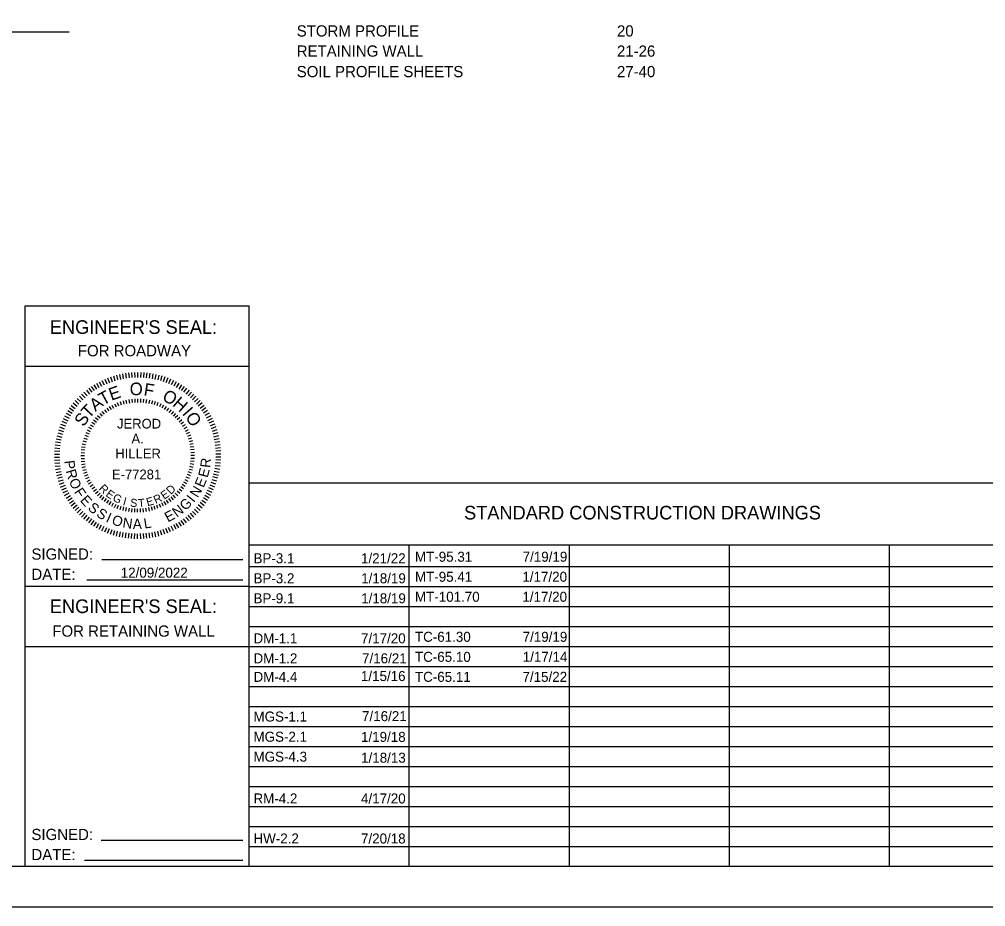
# Model space of a CAD drawing. Extents: x 0 to 34, y 0 to 22.
# Drawn here: x 8.38 to 20.45, y 0 to 11.08 of the extents above; entities that cross this region are included whole.
import ezdxf

# ---------------------------------------------------------------- set-up
doc = ezdxf.new("R2010")
doc.units = 0
for name, color, linetype in [('Default', 7, 'Continuous'), ('SH_Border', 7, 'Continuous'), ('SH_Cut_Line', 7, 'Continuous'), ('SH_Data', 7, 'Continuous'), ('SH_Text', 7, 'Continuous')]:
    doc.layers.add(name, color=color, linetype=linetype)

msp = doc.modelspace()

# ---------------------------------------------------------------- linework, layer by layer
at = {"layer": 'Default'}
for p, q in [((9.629, 6.648), (9.643, 6.586)), ((9.666, 6.656), (9.678, 6.594)), ((9.704, 6.662), (9.713, 6.6)), ((9.742, 6.667), (9.749, 6.604)), ((9.781, 6.67), (9.785, 6.608)), ((9.819, 6.673), (9.821, 6.61)), ((9.857, 6.673), (9.857, 6.61)), ((9.896, 6.673), (9.893, 6.61)), ((9.934, 6.67), (9.929, 6.608)), ((9.972, 6.667), (9.965, 6.604)), ((10.01, 6.662), (10.001, 6.6)), ((10.048, 6.656), (10.037, 6.594)), ((10.086, 6.648), (10.072, 6.586)), ((9.343, 6.537), (9.374, 6.483)), ((9.377, 6.556), (9.406, 6.5)), ((9.411, 6.573), (9.438, 6.516)), ((9.446, 6.589), (9.471, 6.531)), ((9.482, 6.603), (9.505, 6.544)), ((9.518, 6.616), (9.538, 6.557)), ((9.554, 6.628), (9.573, 6.568)), ((9.591, 6.639), (9.607, 6.578)), ((10.123, 6.639), (10.107, 6.578)), ((10.16, 6.628), (10.142, 6.568)), ((10.197, 6.616), (10.176, 6.557)), ((10.233, 6.603), (10.21, 6.544)), ((10.268, 6.589), (10.243, 6.531)), ((10.303, 6.573), (10.276, 6.516)), ((10.338, 6.556), (10.308, 6.5)), ((10.371, 6.537), (10.34, 6.483)), ((9.157, 6.402), (9.2, 6.356)), ((9.186, 6.427), (9.227, 6.379)), ((9.216, 6.452), (9.255, 6.402)), ((9.246, 6.475), (9.283, 6.424)), ((9.278, 6.497), (9.313, 6.445)), ((9.31, 6.518), (9.343, 6.464)), ((10.404, 6.518), (10.371, 6.464)), ((10.437, 6.497), (10.402, 6.445)), ((10.468, 6.475), (10.431, 6.424)), ((10.499, 6.452), (10.46, 6.402)), ((10.529, 6.427), (10.488, 6.379)), ((10.557, 6.402), (10.515, 6.356)), ((9.052, 6.291), (9.1, 6.251)), ((9.076, 6.32), (9.124, 6.278)), ((9.102, 6.348), (9.148, 6.305)), ((9.129, 6.376), (9.173, 6.331)), ((9.569, 6.281), (9.587, 6.241)), ((9.603, 6.296), (9.619, 6.254)), ((9.638, 6.308), (9.652, 6.266)), ((9.674, 6.319), (9.685, 6.276)), ((9.71, 6.327), (9.719, 6.284)), ((9.746, 6.334), (9.753, 6.29)), ((9.783, 6.339), (9.788, 6.295)), ((9.82, 6.342), (9.822, 6.298)), ((9.857, 6.343), (9.857, 6.299)), ((9.894, 6.342), (9.892, 6.298)), ((9.931, 6.339), (9.927, 6.295)), ((9.968, 6.334), (9.961, 6.29)), ((10.005, 6.327), (9.995, 6.284)), ((10.041, 6.319), (10.029, 6.276)), ((10.076, 6.308), (10.063, 6.266)), ((10.111, 6.296), (10.095, 6.254)), ((10.145, 6.281), (10.128, 6.241)), ((10.585, 6.376), (10.541, 6.331)), ((10.612, 6.348), (10.566, 6.305)), ((10.638, 6.32), (10.591, 6.278)), ((10.663, 6.291), (10.614, 6.251)), ((8.964, 6.165), (9.018, 6.133)), ((8.984, 6.197), (9.037, 6.163)), ((9.005, 6.229), (9.057, 6.193)), ((9.028, 6.26), (9.078, 6.222)), ((9.383, 6.161), (9.413, 6.128)), ((9.411, 6.185), (9.439, 6.15)), ((9.441, 6.207), (9.467, 6.172)), ((9.471, 6.228), (9.495, 6.191)), ((9.503, 6.248), (9.525, 6.21)), ((9.536, 6.265), (9.556, 6.226)), ((10.179, 6.265), (10.159, 6.226)), ((10.212, 6.248), (10.189, 6.21)), ((10.243, 6.228), (10.219, 6.191)), ((10.274, 6.207), (10.248, 6.172)), ((10.303, 6.185), (10.275, 6.15)), ((10.331, 6.161), (10.302, 6.128)), ((10.687, 6.26), (10.636, 6.222)), ((10.709, 6.229), (10.658, 6.193)), ((10.731, 6.197), (10.678, 6.163)), ((10.751, 6.165), (10.697, 6.133)), ((8.911, 6.063), (8.968, 6.037)), ((8.927, 6.097), (8.983, 6.069)), ((8.945, 6.131), (9, 6.101)), ((9.284, 6.051), (9.32, 6.025)), ((9.307, 6.08), (9.341, 6.052)), ((9.331, 6.108), (9.363, 6.079)), ((9.356, 6.135), (9.387, 6.104)), ((10.358, 6.135), (10.327, 6.104)), ((10.384, 6.108), (10.351, 6.079)), ((10.408, 6.08), (10.374, 6.052)), ((10.43, 6.051), (10.395, 6.025)), ((10.77, 6.131), (10.714, 6.101)), ((10.788, 6.097), (10.731, 6.069)), ((10.804, 6.063), (10.747, 6.037)), ((8.858, 5.919), (8.918, 5.901)), ((8.869, 5.955), (8.929, 5.936)), ((8.881, 5.992), (8.941, 5.97)), ((8.895, 6.027), (8.954, 6.004)), ((9.21, 5.922), (9.25, 5.904)), ((9.226, 5.956), (9.265, 5.936)), ((9.244, 5.988), (9.282, 5.966)), ((9.263, 6.02), (9.3, 5.996)), ((10.452, 6.02), (10.415, 5.996)), ((10.471, 5.988), (10.433, 5.966)), ((10.489, 5.956), (10.449, 5.936)), ((10.505, 5.922), (10.464, 5.904)), ((10.819, 6.027), (10.761, 6.004)), ((10.833, 5.992), (10.774, 5.97)), ((10.846, 5.955), (10.786, 5.936)), ((10.857, 5.919), (10.796, 5.901)), ((8.832, 5.806), (8.894, 5.796)), ((8.839, 5.844), (8.901, 5.831)), ((8.848, 5.881), (8.909, 5.866)), ((9.173, 5.817), (9.215, 5.806)), ((9.183, 5.853), (9.225, 5.839)), ((9.196, 5.888), (9.237, 5.872)), ((10.519, 5.888), (10.478, 5.872)), ((10.531, 5.853), (10.489, 5.839)), ((10.542, 5.817), (10.499, 5.806)), ((10.867, 5.881), (10.805, 5.866)), ((10.875, 5.844), (10.813, 5.831)), ((10.882, 5.806), (10.82, 5.796)), ((8.82, 5.692), (8.883, 5.688)), ((8.822, 5.73), (8.885, 5.724)), ((8.827, 5.768), (8.889, 5.76)), ((9.153, 5.708), (9.196, 5.704)), ((9.157, 5.745), (9.201, 5.738)), ((9.164, 5.781), (9.207, 5.772)), ((10.55, 5.781), (10.507, 5.772)), ((10.557, 5.745), (10.514, 5.738)), ((10.562, 5.708), (10.518, 5.704)), ((10.888, 5.768), (10.825, 5.76)), ((10.892, 5.73), (10.829, 5.724)), ((10.895, 5.692), (10.832, 5.688)), ((8.818, 5.653), (8.881, 5.652)), ((8.818, 5.615), (8.881, 5.616)), ((8.82, 5.577), (8.883, 5.58)), ((9.149, 5.634), (9.193, 5.634)), ((9.15, 5.671), (9.194, 5.669)), ((9.15, 5.597), (9.194, 5.599)), ((9.153, 5.56), (9.196, 5.565)), ((10.562, 5.56), (10.518, 5.565)), ((10.565, 5.671), (10.521, 5.669)), ((10.565, 5.597), (10.521, 5.599)), ((10.566, 5.634), (10.522, 5.634)), ((10.895, 5.577), (10.832, 5.58)), ((10.896, 5.653), (10.833, 5.652)), ((10.896, 5.615), (10.833, 5.616)), ((8.822, 5.538), (8.885, 5.544)), ((8.827, 5.5), (8.889, 5.508)), ((8.832, 5.462), (8.894, 5.472)), ((8.839, 5.424), (8.901, 5.437)), ((9.157, 5.523), (9.201, 5.53)), ((9.164, 5.487), (9.207, 5.496)), ((9.173, 5.451), (9.215, 5.462)), ((10.542, 5.451), (10.499, 5.462)), ((10.55, 5.487), (10.507, 5.496)), ((10.557, 5.523), (10.514, 5.53)), ((10.875, 5.424), (10.813, 5.437)), ((10.882, 5.462), (10.82, 5.472)), ((10.888, 5.5), (10.825, 5.508)), ((10.892, 5.538), (10.829, 5.544)), ((8.848, 5.387), (8.909, 5.402)), ((8.858, 5.35), (8.918, 5.367)), ((8.869, 5.313), (8.929, 5.332)), ((9.183, 5.415), (9.225, 5.429)), ((9.196, 5.38), (9.237, 5.396)), ((9.21, 5.346), (9.25, 5.364)), ((9.226, 5.312), (9.265, 5.332)), ((10.489, 5.312), (10.449, 5.332)), ((10.505, 5.346), (10.464, 5.364)), ((10.519, 5.38), (10.478, 5.396)), ((10.531, 5.415), (10.489, 5.429)), ((10.846, 5.313), (10.786, 5.332)), ((10.857, 5.35), (10.796, 5.367)), ((10.867, 5.387), (10.805, 5.402)), ((8.881, 5.277), (8.941, 5.298)), ((8.895, 5.241), (8.954, 5.265)), ((8.911, 5.206), (8.968, 5.232)), ((8.927, 5.171), (8.983, 5.199)), ((9.244, 5.28), (9.282, 5.302)), ((9.263, 5.248), (9.3, 5.272)), ((9.284, 5.218), (9.32, 5.244)), ((9.307, 5.188), (9.341, 5.216)), ((10.408, 5.188), (10.374, 5.216)), ((10.43, 5.218), (10.395, 5.244)), ((10.452, 5.248), (10.415, 5.272)), ((10.471, 5.28), (10.433, 5.302)), ((10.788, 5.171), (10.731, 5.199)), ((10.804, 5.206), (10.747, 5.232)), ((10.819, 5.241), (10.761, 5.265)), ((10.833, 5.277), (10.774, 5.298)), ((8.945, 5.137), (9, 5.167)), ((8.964, 5.103), (9.018, 5.136)), ((8.984, 5.071), (9.037, 5.105)), ((9.005, 5.039), (9.057, 5.075)), ((9.331, 5.16), (9.363, 5.189)), ((9.356, 5.133), (9.387, 5.164)), ((9.383, 5.108), (9.413, 5.14)), ((9.411, 5.083), (9.439, 5.118)), ((9.441, 5.061), (9.467, 5.097)), ((9.471, 5.04), (9.495, 5.077)), ((10.243, 5.04), (10.219, 5.077)), ((10.274, 5.061), (10.248, 5.097)), ((10.303, 5.083), (10.275, 5.118)), ((10.331, 5.108), (10.302, 5.14)), ((10.358, 5.133), (10.327, 5.164)), ((10.384, 5.16), (10.351, 5.189)), ((10.709, 5.039), (10.658, 5.075)), ((10.731, 5.071), (10.678, 5.105)), ((10.751, 5.103), (10.697, 5.136)), ((10.77, 5.137), (10.714, 5.167)), ((9.028, 5.008), (9.078, 5.046)), ((9.052, 4.978), (9.1, 5.017)), ((9.076, 4.948), (9.124, 4.99)), ((9.102, 4.92), (9.148, 4.963)), ((9.503, 5.02), (9.525, 5.059)), ((9.536, 5.003), (9.556, 5.042)), ((9.569, 4.987), (9.587, 5.027)), ((9.603, 4.973), (9.619, 5.014)), ((9.638, 4.96), (9.652, 5.002)), ((9.674, 4.95), (9.685, 4.992)), ((9.71, 4.941), (9.719, 4.984)), ((9.746, 4.934), (9.753, 4.978)), ((9.783, 4.929), (9.788, 4.973)), ((9.82, 4.927), (9.822, 4.971)), ((9.857, 4.926), (9.857, 4.97)), ((9.894, 4.927), (9.892, 4.971)), ((9.931, 4.929), (9.927, 4.973)), ((9.968, 4.934), (9.961, 4.978)), ((10.005, 4.941), (9.995, 4.984)), ((10.041, 4.95), (10.029, 4.992)), ((10.076, 4.96), (10.063, 5.002)), ((10.111, 4.973), (10.095, 5.014)), ((10.145, 4.987), (10.128, 5.027)), ((10.179, 5.003), (10.159, 5.042)), ((10.212, 5.02), (10.189, 5.059)), ((10.612, 4.92), (10.566, 4.963)), ((10.638, 4.948), (10.591, 4.99)), ((10.663, 4.978), (10.614, 5.017)), ((10.687, 5.008), (10.636, 5.046)), ((9.129, 4.893), (9.173, 4.937)), ((9.157, 4.866), (9.2, 4.913)), ((9.186, 4.841), (9.227, 4.889)), ((9.216, 4.817), (9.255, 4.866)), ((9.246, 4.793), (9.283, 4.844)), ((10.468, 4.793), (10.431, 4.844)), ((10.499, 4.817), (10.46, 4.866)), ((10.529, 4.841), (10.488, 4.889)), ((10.557, 4.866), (10.515, 4.913)), ((10.585, 4.893), (10.541, 4.937)), ((9.278, 4.771), (9.313, 4.824)), ((9.31, 4.751), (9.343, 4.804)), ((9.343, 4.731), (9.374, 4.786)), ((9.377, 4.713), (9.406, 4.768)), ((9.411, 4.695), (9.438, 4.752)), ((9.446, 4.68), (9.471, 4.737)), ((9.482, 4.665), (9.505, 4.724)), ((9.518, 4.652), (9.538, 4.711)), ((10.197, 4.652), (10.176, 4.711)), ((10.233, 4.665), (10.21, 4.724)), ((10.268, 4.68), (10.243, 4.737)), ((10.303, 4.695), (10.276, 4.752)), ((10.338, 4.713), (10.308, 4.768)), ((10.371, 4.731), (10.34, 4.786)), ((10.404, 4.751), (10.371, 4.804)), ((10.437, 4.771), (10.402, 4.824)), ((9.554, 4.64), (9.573, 4.7)), ((9.591, 4.629), (9.607, 4.69)), ((9.629, 4.62), (9.643, 4.682)), ((9.666, 4.613), (9.678, 4.674)), ((9.704, 4.606), (9.713, 4.669)), ((9.742, 4.601), (9.749, 4.664)), ((9.781, 4.598), (9.785, 4.661)), ((9.819, 4.596), (9.821, 4.659)), ((9.857, 4.595), (9.857, 4.658)), ((9.896, 4.596), (9.893, 4.659)), ((9.934, 4.598), (9.929, 4.661)), ((9.972, 4.601), (9.965, 4.664)), ((10.01, 4.606), (10.001, 4.669)), ((10.048, 4.613), (10.037, 4.674)), ((10.086, 4.62), (10.072, 4.682)), ((10.123, 4.629), (10.107, 4.69)), ((10.16, 4.64), (10.142, 4.7))]:
    msp.add_line(p, q, dxfattribs=at)
at = {"layer": 'SH_Border'}
for p, q in [((9.408, 4.334), (11.171, 4.334)), ((9.222, 4.082), (11.171, 4.082)), ((9.401, 0.832), (11.171, 0.832)), ((9.193, 0.581), (11.171, 0.581))]:
    msp.add_line(p, q, dxfattribs=at)
at = {"layer": 'SH_Cut_Line'}
for p, q in [((9, 10.922), (7.75, 10.922)), ((8.45, 3.75), (8.45, 7.504)), ((8.45, 7.504), (11.25, 7.504)), ((11.25, 0.5), (11.25, 7.504)), ((8.45, 6.752), (11.25, 6.752)), ((11.25, 5.292), (24.7, 5.292)), ((11.25, 4.521), (24.7, 4.521)), ((13.25, 0.5), (13.25, 4.521)), ((15.25, 0.5), (15.25, 4.521)), ((17.25, 0.5), (17.25, 4.521)), ((19.25, 0.5), (19.25, 4.521)), ((11.25, 4.25), (24.7, 4.25)), ((8.45, 4.002), (11.25, 4.002)), ((11.25, 4), (24.7, 4)), ((8.45, 0.5), (8.45, 3.75)), ((11.25, 3.75), (24.7, 3.75)), ((11.25, 3.5), (24.7, 3.5)), ((8.45, 3.25), (11.25, 3.25)), ((11.25, 3.25), (24.7, 3.25)), ((11.25, 3), (24.7, 3)), ((11.25, 2.75), (24.7, 2.75)), ((11.25, 2.5), (24.7, 2.5)), ((11.25, 2.25), (24.7, 2.25)), ((11.25, 2), (24.7, 2)), ((11.25, 1.75), (24.7, 1.75)), ((11.25, 1.5), (24.7, 1.5)), ((11.25, 1.25), (24.7, 1.25)), ((11.25, 1), (24.7, 1)), ((11.25, 0.75), (24.7, 0.75))]:
    msp.add_line(p, q, dxfattribs=at)
at = {"layer": 'SH_Data'}
msp.add_lwpolyline([(1.5, 21.5), (33.5, 21.5), (33.5, 0.5), (1.5, 0.5)], close=True, dxfattribs=at)
at = {"layer": 'SH_Text'}
msp.add_lwpolyline([(0, 0), (34, 0), (34, 22), (0, 22)], close=True, dxfattribs=at)

# ---------------------------------------------------------------- texts
at = {"layer": 'Default'}
for s, height, rotation, p in [('O', 0.157, 0.9655, (9.759, 6.387)), ('F', 0.157, 351.1051, (9.926, 6.386)), ('T', 0.157, 28.4655, (9.423, 6.257)), ('E', 0.157, 19.2989, (9.528, 6.318)), ('O', 0.157, 330.5739, (10.152, 6.334)), ('T', 0.157, 46.7989, (9.249, 6.088)), ('A', 0.157, 37.6322, (9.329, 6.179)), ('H', 0.157, 319.2312, (10.282, 6.263)), ('S', 0.157, 55.9655, (9.184, 5.986)), ('I', 0.157, 311.2054, (10.406, 6.156)), ('O', 0.157, 304.2146, (10.446, 6.113)), ('P', 0.126, 277.3994, (8.941, 5.567)), ('R', 0.126, 84.0805, (10.763, 5.477)), ('R', 0.126, 285.8994, (8.957, 5.443)), ('E', 0.126, 75.5805, (10.731, 5.351)), ('O', 0.126, 294.3994, (8.994, 5.317)), ('E', 0.126, 67.0805, (10.68, 5.225)), ('F', 0.126, 302.8994, (9.058, 5.18)), ('R', 0.101, 314.904, (9.366, 5.216)), ('E', 0.101, 324.904, (9.45, 5.134)), ('E', 0.101, 34.904, (10.188, 5.081)), ('D', 0.101, 44.904, (10.273, 5.141)), ('N', 0.126, 58.5805, (10.606, 5.1)), ('E', 0.126, 311.3994, (9.131, 5.071)), ('G', 0.101, 334.904, (9.536, 5.074)), ('I', 0.101, 344.904, (9.666, 5.019)), ('S', 0.101, 354.904, (9.759, 4.997)), ('T', 0.101, 4.904, (9.867, 4.989)), ('E', 0.101, 14.904, (9.979, 5.001)), ('R', 0.101, 24.904, (10.083, 5.029)), ('G', 0.126, 44.8994, (10.455, 4.938)), ('I', 0.126, 51.6252, (10.556, 5.041)), ('S', 0.126, 319.8994, (9.226, 4.966)), ('S', 0.126, 328.3994, (9.332, 4.881)), ('E', 0.126, 27.8994, (10.235, 4.798)), ('N', 0.126, 36.3994, (10.347, 4.857)), ('I', 0.126, 335.7835, (9.451, 4.811)), ('O', 0.126, 343.1502, (9.525, 4.777)), ('N', 0.126, 352.0551, (9.663, 4.736)), ('A', 0.126, 0.5551, (9.797, 4.718)), ('L', 0.126, 9.0551, (9.943, 4.721))]:
    msp.add_text(s, height=height, rotation=rotation, dxfattribs=at).set_placement(p)
at = {"layer": 'SH_Border'}
for s, height, p in [('STORM PROFILE', 0.14, (11.844, 10.868)), ('20', 0.14, (15.844, 10.868)), ('RETAINING WALL', 0.14, (11.844, 10.616)), ('21-26', 0.14, (15.844, 10.616)), ('SOIL PROFILE SHEETS', 0.14, (11.844, 10.36)), ('27-40', 0.14, (15.844, 10.36)), ("ENGINEER'S SEAL:", 0.17, (8.76, 7.154)), ('FOR ROADWAY', 0.14, (9.11, 6.874)), ('STANDARD CONSTRUCTION DRAWINGS', 0.17, (13.934, 4.836)), ('SIGNED:', 0.14, (8.53, 4.334)), ('BP-3.1', 0.125, (11.304, 4.289)), ('1/21/22', 0.125, (12.647, 4.289)), ('MT-95.31', 0.125, (13.321, 4.308)), ('7/19/19', 0.125, (14.666, 4.308)), ('12/09/2022', 0.125, (9.646, 4.109)), ('DATE:', 0.14, (8.53, 4.082)), ('BP-3.2', 0.125, (11.304, 4.039)), ('1/18/19', 0.125, (12.649, 4.039)), ('MT-95.41', 0.125, (13.321, 4.058)), ('1/17/20', 0.125, (14.663, 4.058)), ('BP-9.1', 0.125, (11.304, 3.789)), ('1/18/19', 0.125, (12.649, 3.789)), ('MT-101.70', 0.125, (13.321, 3.808)), ('1/17/20', 0.125, (14.663, 3.808)), ("ENGINEER'S SEAL:", 0.17, (8.76, 3.667)), ('FOR RETAINING WALL', 0.14, (8.791, 3.372)), ('DM-1.1', 0.125, (11.304, 3.289)), ('7/17/20', 0.125, (12.647, 3.289)), ('TC-61.30', 0.125, (13.321, 3.308)), ('7/19/19', 0.125, (14.666, 3.308)), ('DM-1.2', 0.125, (11.304, 3.039)), ('7/16/21', 0.125, (12.66, 3.039)), ('TC-65.10', 0.125, (13.321, 3.058)), ('1/17/14', 0.125, (14.667, 3.058)), ('DM-4.4', 0.125, (11.304, 2.808)), ('1/15/16', 0.125, (12.646, 2.818)), ('TC-65.11', 0.125, (13.321, 2.808)), ('7/15/22', 0.125, (14.664, 2.808)), ('MGS-1.1', 0.125, (11.304, 2.312)), ('7/16/21', 0.125, (12.66, 2.317)), ('MGS-2.1', 0.125, (11.304, 2.06)), ('1/19/18', 0.125, (12.647, 2.058)), ('MGS-4.3', 0.125, (11.304, 1.811)), ('1/18/13', 0.125, (12.648, 1.798)), ('RM-4.2', 0.125, (11.304, 1.289)), ('4/17/20', 0.125, (12.647, 1.289)), ('SIGNED:', 0.14, (8.53, 0.832)), ('HW-2.2', 0.125, (11.304, 0.789)), ('7/20/18', 0.125, (12.647, 0.789)), ('DATE:', 0.14, (8.53, 0.581))]:
    msp.add_text(s, height=height, dxfattribs=at).set_placement(p)
at = {"layer": 'SH_Cut_Line'}
for s, p in [('JEROD', (9.599, 5.972)), ('A.', (9.78, 5.786)), ('HILLER', (9.578, 5.599)), ('E-77281', (9.536, 5.338))]:
    msp.add_text(s, height=0.1216, dxfattribs=at).set_placement(p)

doc.saveas('drawing.dxf')
